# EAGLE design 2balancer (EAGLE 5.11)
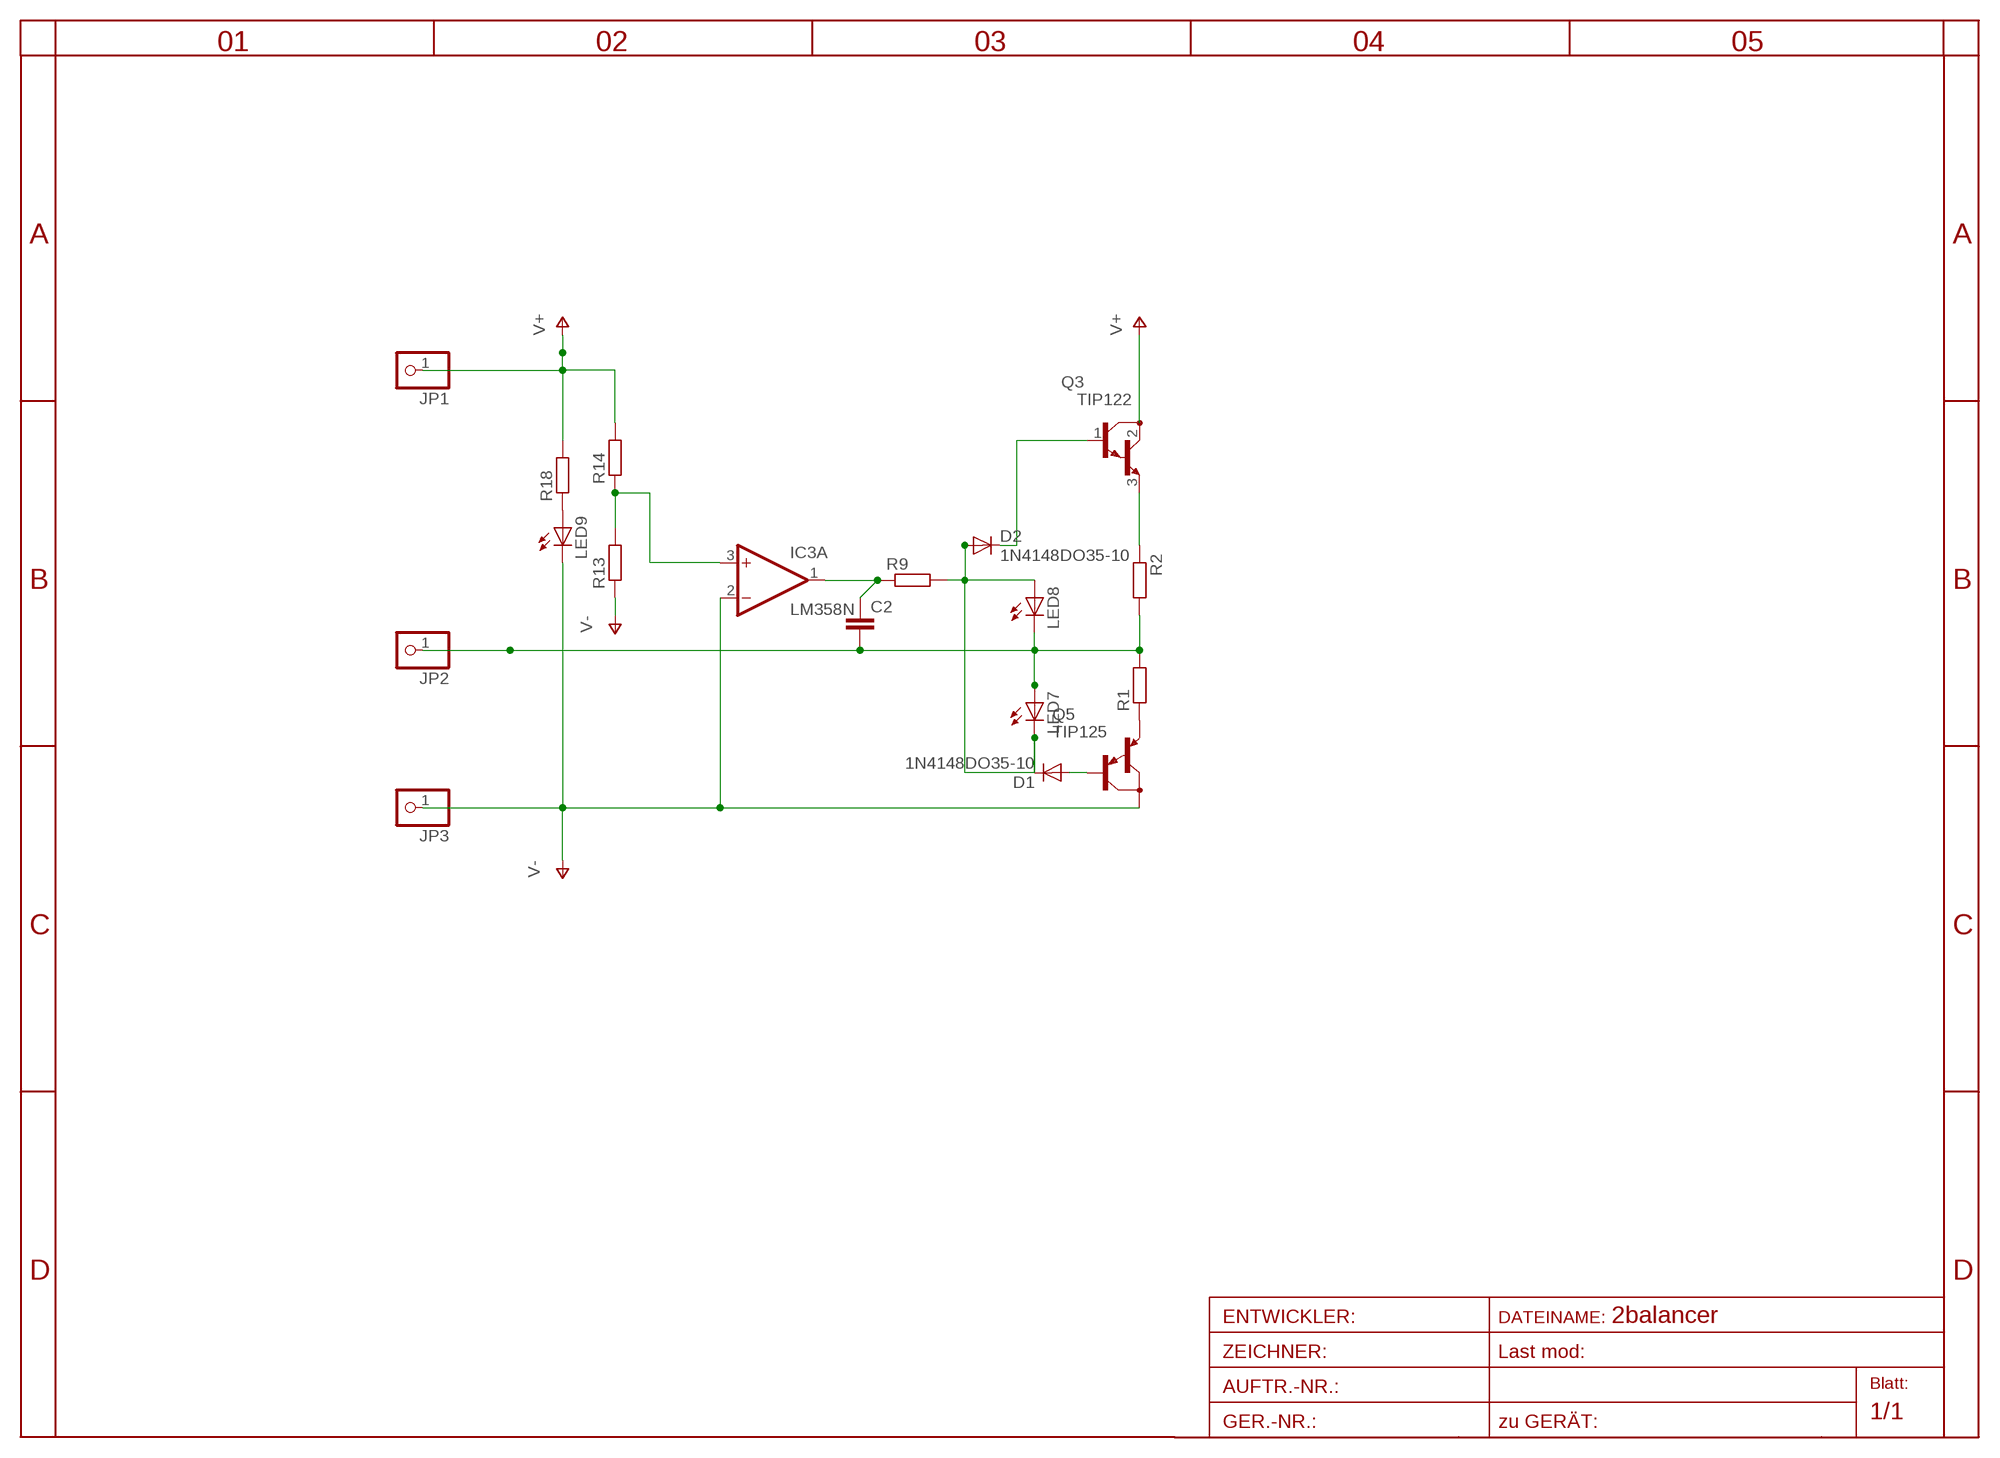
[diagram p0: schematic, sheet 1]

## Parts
C2  C-EU025-024X044  [C025-024X044]
D1  1N4148DO35-10  [DO35-10]
D2  1N4148DO35-10  [DO35-10]
IC3  LM358N  [DIL08]
JP1  PINHD-1X11MM6  [1X1MM8]
JP2  PINHD-1X11MM6  [1X1MM8]
JP3  PINHD-1X11MM6  [1X1MM8]
LED7  LED3MM  [LED3MM]
LED8  LED3MM  [LED3MM]
LED9  LED3MM  [LED3MM]
Q3  TIP122  [TO220]
Q5  TIP125  [TO220]
R1  R-EU_0207/10  [0207/10]
R2  R-EU_0207/10  [0207/10]
R9  R-EU_0204/5  [0204/5]
R13  R-EU_0204/5  [0204/5]
R14  R-EU_0204/5  [0204/5]
R18  R-EU_0204/5  [0204/5]

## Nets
B1: C2.2 JP2.1 LED7.A LED8.K(C) R1.2 R2.2
N$1: D1.A Q5.1(B)
N$2: D2.C Q3.1(B)
N$9: D1.C D2.A LED7.K(C) LED8.A R9.2
N$13: Q5.3(E) R1.1
N$25: C2.1 IC3.1(A:OUT) R9.1
N$27: Q3.3(E) R2.1
N$28: IC3.3(A:+IN) R13.2 R14.1
N$34: LED9.A R18.1
V+: JP1.1 Q3.2(C) R14.2 R18.2
V-: IC3.2(A:-IN) JP3.1 LED9.K(C) Q5.2(C) R13.1
Unconnected: IC3.5(B:+IN) IC3.6(B:-IN) IC3.7(B:OUT)

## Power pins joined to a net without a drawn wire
V+: IC3.8(P:V+)
V-: IC3.4(P:V-)

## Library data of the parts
C2 = rcl-2:C-EU: CAPACITOR, European symbol
D1 D2 = diode-1:1N4148: DIODE
IC3 = linear:LM358: OP AMP also LM158; LM258; LM2904 Source: http://cache.national.com/ds/LM/LM158.pdf
JP1-JP3 = pinhead:PINHD-1X1: PIN HEADER
LED7-LED9 = led:LED: LED
Q3 = transistor-npn:TIP122*: NPN Darlington Transistor
Q5 = transistor-pnp:TIP125: PNP Transistor
R1 R2 R9 R13 R14 R18 = rcl-2:R-EU_: RESISTOR, European symbol

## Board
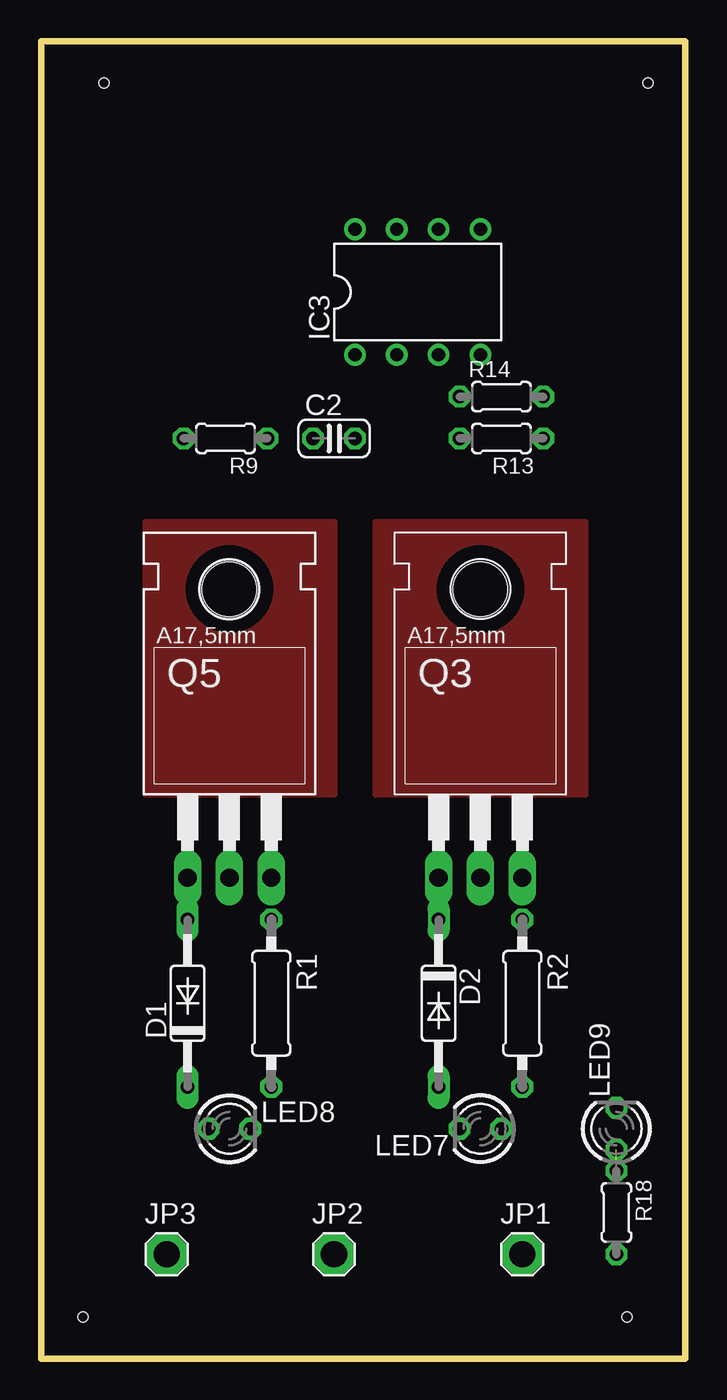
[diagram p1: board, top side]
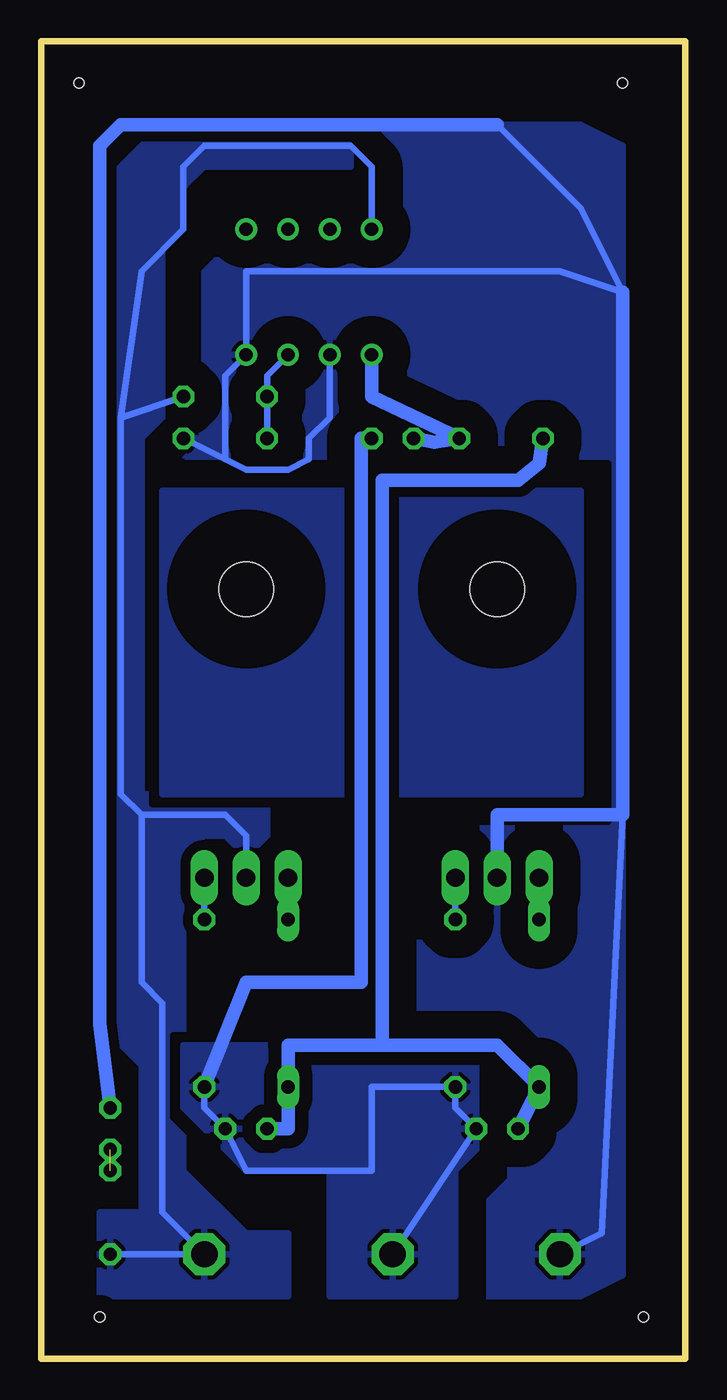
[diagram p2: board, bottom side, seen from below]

Size 39.12 x 80 mm. Coordinates in mm from the lower left corner, seen from the top.
Outline: 0,0 39.12,0 39.12,80 0,80 0,0
Copper layers (1*16): Top 0.035mm / dielectric 1.5mm / Bottom 0.035mm
Design rules "default": minimum track width 10mil, minimum drill 24mil, track to track 8mil, track to pad 8mil, pad to pad 8mil, via to via 8mil, smd to smd 8mil, copper to edge 40mil, drill to drill 8mil, minimum pad ring 10mil, minimum via ring 8mil, stop-mask expansion 4mil, vias tented up to drill 0mil, thermal gap 10mil
Holes 0.6 mm at 2.54,2.54 35.56,2.54 36.83,77.47 3.81,77.47

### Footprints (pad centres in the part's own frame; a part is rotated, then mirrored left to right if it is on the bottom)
C025-024X044 = drill 0.813 octagon: 1 -1.27,0; 2 1.27,0
DO35-10 = drill 0.813 long: A 5.08,0; C -5.08,0
DIL08 = drill 0.813 pad 1.27 round: 1 -3.81,-3.81; 2 -1.27,-3.81; 3 1.27,-3.81; 4 3.81,-3.81; 5 3.81,3.81; 6 1.27,3.81; 7 -1.27,3.81; 8 -3.81,3.81
1X1MM8 = drill 1.6 pad 2.54 octagon: 1 0,0
LED3MM = drill 0.813 octagon: A -1.27,0; K 1.27,0
TO220 = drill 1.118 long: 1 -2.54,-6.35; 2 0,-6.35; 3 2.54,-6.35 | hole 3.302: 0,11.176
0207/10 = drill 0.813 octagon: 1 -5.08,0; 2 5.08,0
0204/5 = drill 0.813 octagon: 1 -2.54,0; 2 2.54,0

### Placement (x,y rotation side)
C2  17.78,55.88 0 top
D1  8.89,21.59 90 top
D2  24.13,21.59 270 top
IC3  22.86,64.77 0 top
JP1  29.21,6.35 0 top
JP2  17.78,6.35 0 top
JP3  7.62,6.35 0 top
LED7  26.67,13.97 180 top
LED8  11.43,13.97 0 top
LED9  34.92,13.97 90 top
Q3  26.67,35.56 0 top
Q5  11.43,35.56 0 top
R1  13.97,21.59 270 top
R2  29.21,21.59 270 top
R9  11.19,55.88 180 top
R13  27.94,55.88 180 top
R14  27.94,58.42 0 top
R18  34.92,8.89 270 top

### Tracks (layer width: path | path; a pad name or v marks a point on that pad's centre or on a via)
B1
  Bottom 0.406: 19.68,55.88 C2.2 | JP2.1 LED8.K 13.97,15.24 R1.2 19.05,16.51 19.05,11.43 26.67,11.43 LED7.A 29.21,15.24 R2.2
  Bottom 0.813: R2.2 26.67,22.86 19.68,22.86 19.68,55.88
  pour Bottom (isolate 0.813, rank 3): 13.97,3.81 13.97,11.43 12.7,12.7 12.7,17.78 13.97,19.05 30.48,19.05 30.48,15.24 26.67,11.43 21.59,11.43 21.59,3.81
N$1
  Bottom 0.406: D1.A Q5.1
N$2
  Bottom 0.406: D2.C Q3.1
N$9
  Bottom 0.813: 18.41,19.05 11.43,19.05 D1.C LED8.A | 18.41,19.05 24.13,19.05 D2.A 24.13,13.97 LED7.K | 18.41,19.05 18.41,53.34 10.16,53.34 8.89,54.37 R9.2
N$13
  Bottom 0.406: R1.1 Q5.3
N$25
  Bottom 0.813: C2.1 15.24,55.64 R9.1 19.05,58.42 IC3.1
N$27
  Bottom 0.406: R2.1 Q3.3
N$28
  Bottom 0.406: R13.2 R14.1 25.4,59.69 IC3.3
N$31
  pour Top (isolate 0.61, rank 4): 6.35,50.8 17.78,50.8 17.78,34.29 6.35,34.29
  pour Top (isolate 0.61, rank 4): 20.32,50.8 33.02,50.8 33.02,34.29 20.32,34.29
  pour Bottom (isolate 0.61, rank 4): 6.35,52.7 17.78,52.7 17.78,34.29 6.35,34.29
  pour Bottom (isolate 0.61, rank 3): 20.32,52.7 31.75,52.7 31.75,34.29 20.32,34.29
N$34  (1 unrouted)
V+
  Bottom 0.406: Q3.2 26.67,31.75 27.94,33.02 33.02,33.02 | 33.02,33.02 34.29,34.29 34.29,57.15 | 34.29,57.15 33.02,66.04 30.48,68.58 30.48,72.39 29.21,73.66 20.32,73.66 19.05,72.39 IC3.8 | 34.29,57.15 R14.2 | R18.2 JP1.1 31.75,8.89 31.75,21.59 33.02,22.86 33.02,33.02
  pour Bottom (isolate 0.61, rank 4): 33.02,8.89 35.56,8.89 35.56,3.81 24.13,3.81 24.13,7.62 26.67,7.62 30.48,11.43 30.48,30.48 29.21,31.75 27.94,31.75 26.67,30.48 25.4,31.75 25.4,34.29 33.02,34.29 33.02,55.88 31.75,57.15 31.75,67.31 30.48,68.58 30.48,71.12 29.21,72.39 20.32,72.39 20.32,73.66 21.59,74.93 31.75,74.93 35.56,71.12 35.56,20.32 33.02,17.78
V-
  Bottom 0.406: 11.43,74.93 6.35,69.85 3.81,64.77 7.62,66.04 26.67,66.04 IC3.4 27.94,59.69 27.94,54.61 R13.1 26.67,53.98 24.13,53.98 22.86,54.61 22.86,55.88 21.59,57.15 IC3.2 | JP3.1 5.08,7.62 3.81,33.02
  Bottom 0.813: 3.81,64.77 3.81,33.02 11.43,33.02 Q5.2 | LED9.K 35.56,20.32 35.56,73.66 34.29,74.93 11.43,74.93
  pour Bottom (isolate 1.676, rank 5): 24.13,3.81 6.35,3.81 3.81,5.08 3.81,73.66 6.35,74.93 26.67,74.93 29.21,72.39 29.21,58.42 31.75,55.88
